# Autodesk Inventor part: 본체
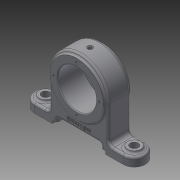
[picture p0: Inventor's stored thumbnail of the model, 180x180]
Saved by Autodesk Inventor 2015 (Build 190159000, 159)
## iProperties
Created: 2019-05
Part Number: 본체
Material: 알루미늄 6061
Document SubType Name: Modeling
Designer: CAD02
Density: 2.7 g/cm^3
Appearance: 기본값
Mass: 454.985 g
Surface Area: 318.799 cm^2
Volume: 168.513 cm^3
Author: CAD02
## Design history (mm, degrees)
sketch "스케치1"
  geometry: L1 (75, 15)-(-75, 15); L2 (-75, 15)-(-75, -15); L3 (-75, -15)-(75, -15); L4 (75, -15)-(75, 15); L5 (75, 15)-(-75, -15); L6 (-75, 15)-(75, -15); 1 further point
  constraints: 12 end point, 2 midpoint, 2 parallel, 1 horizontal, 1 perpendicular
  dimensions: "d0" = 30 distance of L1.end L2.end; "d1" = 150 distance of L1.start L1.end
extrude "돌출1" new body sketch "스케치1" distance "d2" = 12; taper "d3" = 0 deg
fillet "모깎기1" dims "d4" = 15
sketch "스케치2"
  geometry: C1 r 9 at (-60, 0); A1 r 15 centre (-60, 0) between (-60, 15) and (-60, -15) reference; 1 further point
  constraints: 1 centre point, 1 coincident
  dimensions: "d5" = 18 diameter of C1
extrude "돌출2" join sketch "스케치2" distance "d6" = 3; taper "d7" = 0 deg
sketch "스케치3"
  geometry: C1 r 9 at (0, 0) reference; 1 further point
hole "구멍1" sketch "스케치3" at (0, 0) diameter "d8" = 11; stored, may be unused: countersink angle "d12" = 90 deg, drill point angle "d14" = 0 deg; dims "d9" = 6, "d10" = 4, "d11" = 2, "d13" = 8
sketch "스케치4"
  geometry: L1 (0, 0)-(120, 0) reference; L2 (30, 0)-(90, 0); L3 (90, 0)-(90, 10); L4 (90, 10)-(30, 10); L5 (30, 10)-(30, 0); 3 further points
  constraints: 8 end point, 2 midpoint, 2 parallel, 1 coincident, 1 horizontal, 1 perpendicular, 1 point on line
  dimensions: "d15" = 10 distance of L2.end L3.end; "d16" = 60 distance between parallel lines of L3 L5
extrude "돌출3" cut sketch "스케치4" stored distance "d18" = 3; taper "d19" = 0 deg
sketch "스케치5"
  geometry: L1 (0, -12)-(30, -12) reference; L2 (24, -12)-(96, -12); L3 (96, -12)-(96, -8); L4 (96, -8)-(24, -8); L5 (24, -8)-(24, -12); 2 further points
  constraints: 8 end point, 2 parallel, 1 coincident, 1 horizontal, 1 midpoint, 1 perpendicular, 1 point on line
  dimensions: "d20" = 4 distance of L4.end L2.start; "d21" = 72 distance of L3.end L4.end
extrude "돌출4" cut sketch "스케치5" stored distance "d22" = 3; taper "d23" = 0 deg
sketch "스케치6"
  geometry: L1 (-60, -15)-(60, -15) reference; L2 (40, 15)-(-40, 15); L3 (-40, 15)-(-40, -15); L4 (-40, -15)-(40, -15); L5 (40, -15)-(40, 15); L6 (40, 15)-(-40, -15); L7 (-40, 15)-(40, -15); 1 further point
  constraints: 12 end point, 2 midpoint, 2 parallel, 1 horizontal, 1 perpendicular, 1 point on line
  dimensions: "d24" = 80 distance between parallel lines of L3 L5
extrude "돌출5" join sketch "스케치6" distance "d25" = 48; taper "d26" = 0 deg
sketch "스케치7"
  geometry: L1 (-20, 60)-(-100, 60) reference; 2 further points
  constraints: 1 horizontal alignment, 1 midpoint, 2 other
extrude "돌출6" join sketch "스케치7" distance "d27" = 30; taper "d28" = 0 deg
sketch "스케치8"
  geometry: L1 (75, 0)-(65.5, 0) reference; L2 (65.5, 0)-(65.5, 15) reference; L3 (65.5, 15)-(69, 15) reference; L4 (69, 15)-(69, 12) reference; L5 (69, 12)-(75, 12) reference; L6 (75, 12)-(75, 0) reference; L7 (-54.5, 0)-(-54.5, 15) reference; L8 (-54.5, 15)-(-51, 15) reference; L9 (-51, 15)-(-51, 12) reference; L10 (-51, 12)-(-40, 12) reference; L11 (-40, 12)-(-40, 60) reference; L12 (40, 60)-(40, 12) reference; L13 (40, 12)-(51, 12) reference; L14 (51, 12)-(51, 15) reference; L15 (51, 15)-(54.5, 15) reference; L16 (54.5, 15)-(54.5, 0) reference; L17 (54.5, 0)-(36, 0) reference; L18 (36, 0)-(36, 4) reference; L19 (36, 4)-(30, 4) reference; L20 (30, 4)-(30, 10) reference; L21 (30, 10)-(-30, 10) reference; L22 (-30, 10)-(-30, 4) reference; L23 (-30, 4)-(-36, 4) reference; L24 (-36, 4)-(-36, 0) reference; L25 (-36, 0)-(-54.5, 0) reference; L26 (-65.5, 15)-(-65.5, 0) reference; L27 (-65.5, 0)-(-75, 0) reference; L28 (-75, 0)-(-75, 12) reference; L29 (-75, 12)-(-69, 12) reference; L30 (-69, 12)-(-69, 15) reference; L31 (-69, 15)-(-65.5, 15) reference; C1 r 36 at (0, 60); A1 r 40 centre (0, 60) between (40, 60) and (-40, 60) reference; 1 further point
  constraints: 1 centre point, 1 coincident
  dimensions: "d29" = 72 diameter of C1
extrude "돌출7" join sketch "스케치8" stored distance "d30" = 36; taper "d31" = 0 deg
sketch "스케치9"
  geometry: C1 r 36 at (0, 0) reference; 1 further point
hole "구멍2" sketch "스케치9" at (0, 0) diameter "d32" = 52; stored, may be unused: countersink angle "d36" = 90 deg, drill point angle "d38" = 0 deg; dims "d33" = 6, "d34" = 4, "d35" = 2, "d37" = 8
sketch "스케치10"
  geometry: C1 r 26 at (0, 0) reference; 2 further points
  constraints: 1 vertical alignment
  dimensions: "d82" = 31 distance of C1.centre point (0, 31)
hole "구멍3" sketch "스케치10" at (0, 31) diameter "d39" = 3.242; stored, may be unused: countersink angle "d43" = 90 deg, drill point angle "d45" = 118 deg; dims "d40" = 6, "d41" = 4, "d42" = 2, "d44" = 8
node "작업 평면1"
sketch "스케치11"
  geometry: C1 r 3.5 at (0, 0); 1 further point
  constraints: 1 centre point, 1 coincident
  dimensions: "d50" = 7 diameter of C1
extrude "돌출8" cut sketch "스케치11" distance "d51" = 1; taper "d52" = 0 deg
sketch "스케치12"
  geometry: C1 r 3.5 at (0, 0) reference
hole "구멍4" sketch "스케치12" at (0, 0) diameter "d53" = 4.917; stored, may be unused: countersink angle "d57" = 90 deg, drill point angle "d59" = 118 deg; dims "d54" = 8, "d55" = 4, "d56" = 2, "d58" = 10
sketch "스케치13"
  geometry: C1 r 2.458 at (0, 0) reference
hole "구멍5" sketch "스케치13" at (0, 0) diameter "d60" = 2; stored, may be unused: countersink angle "d64" = 90 deg, drill point angle "d66" = 0 deg; dims "d61" = 8, "d62" = 4, "d63" = 2, "d65" = 36
sketch "스케치14"
  geometry: 3 further points
  constraints: 2 vertical alignment, 1 other
hole "구멍6" sketch "스케치14" at (0, 26) diameter "d67" = 3; stored, may be unused: countersink angle "d71" = 90 deg, drill point angle "d73" = 0 deg; dims "d68" = 8, "d69" = 4, "d70" = 2, "d72" = 36
fillet "모깎기2" dims "d74" = 6
fillet "모깎기3" dims "d75" = 3
fillet "모깎기4" dims "d76" = 3
fillet "모깎기5" dims "d77" = 3
fillet "모깎기6" dims "d78" = 3
chamfer "모따기1" distance "d79" = 1; stored, may be unused: second distance "d80" = 2, angle "d81" = 45 deg
sketch "스케치15"
  geometry: L1 (-63, 10)-(-9, 10) reference; 2 further points
  constraints: 1 vertical alignment, 1 other
  dimensions: "d83" = 7 distance from line of L1 point (-36, 17)
feature "엠보싱1" sketch "스케치15" dims "d0" = 30, "d1" = 150, "d84" = 0.5, "d85" = 0
node "솔리드1"
mirror "대칭1"
pattern_circular "원형 패턴1" dims angle "d47" = 360 deg
mirror "대칭2"
node "절단 모서리 투영1"
